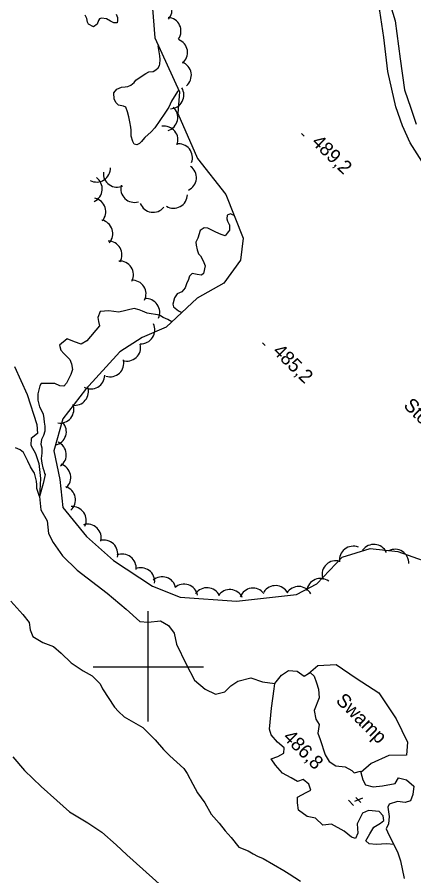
# Model space of a CAD drawing. Extents: x 642515 to 647219, y 6080136 to 6084356.
# Drawn here: x 642771.6 to 642857.9, y 6082154.5 to 6082341.5 of the extents above; entities that cross this region are included whole.
import ezdxf

# ---------------------------------------------------------------- set-up
doc = ezdxf.new("R2010")
doc.units = 0
for name, color, linetype in [('Level 1', 7, 'Continuous'), ('Level 2', 7, 'Continuous'), ('Level 21', 7, 'Continuous'), ('Level 3', 7, 'Continuous'), ('Level 4', 7, 'Continuous'), ('Level 44', 7, 'Continuous'), ('Level 54', 7, 'Continuous'), ('Level 61', 7, 'Continuous'), ('Level 7', 7, 'Continuous')]:
    doc.layers.add(name, color=color, linetype=linetype)

msp = doc.modelspace()

# ---------------------------------------------------------------- linework, layer by layer
at = {"layer": 'Level 1'}
for points in [[(642770.63, 6082180.44), (642773.23, 6082177.51), (642776.83, 6082173.98), (642780.24, 6082170.93), (642782.97, 6082168.49), (642787, 6082166.12), (642790.04, 6082164.02), (642793.11, 6082161.27), (642795.5, 6082159.13)], [(642795.5, 6082159.13), (642803.18, 6082152.26)]]:
    msp.add_lwpolyline(points, dxfattribs=at)
at = {"layer": 'Level 2'}
for points in [[(642793.11, 6082342.13), (642793.4, 6082341.41), (642793.47, 6082340.8), (642793.34, 6082340.23), (642792.65, 6082340.23), (642791.93, 6082340.64), (642791.01, 6082341.16), (642789.94, 6082341.26), (642789.54, 6082341.16), (642789.32, 6082340.74), (642789.04, 6082339.99), (642788.18, 6082339.37), (642787.09, 6082339.96), (642786.94, 6082340.4), (642786.73, 6082341.2), (642786.41, 6082341.96)], [(642806.78, 6082325.61), (642806.49, 6082325.28), (642805.18, 6082323.21), (642804.6, 6082321.88), (642803.74, 6082320.57), (642801.55, 6082317.37), (642800.79, 6082316.51), (642799.39, 6082315.29), (642798.97, 6082314.82), (642798.62, 6082314.44), (642798.2, 6082313.97), (642797.65, 6082313.69), (642797.07, 6082313.83), (642796.75, 6082314.42), (642796.44, 6082315.62), (642796.41, 6082316.88), (642796.33, 6082317.56), (642796.15, 6082318.73), (642795.93, 6082319.78), (642795.58, 6082320.85), (642795.24, 6082321.93), (642794.74, 6082322.15), (642793.67, 6082322.33), (642793.11, 6082322.83), (642792.74, 6082323.62), (642792.62, 6082325.04), (642793.27, 6082325.85), (642794.31, 6082326.23), (642795.12, 6082326.36), (642795.68, 6082326.39), (642796.32, 6082326.67), (642797.06, 6082327.24), (642797.4, 6082327.78), (642798.57, 6082328.58), (642799.63, 6082329.25), (642800.27, 6082329.61), (642801.2, 6082329.7), (642801.79, 6082330.02), (642802.29, 6082330.49), (642802.55, 6082330.95), (642802.66, 6082331.24), (642802.68, 6082332.3), (642802.64, 6082333.11), (642802.44, 6082334.36), (642802.33, 6082334.92), (642802.31, 6082335.28)], [(642818.83, 6082298.32), (642818.48, 6082298.49), (642817.98, 6082298.7), (642817.31, 6082298.38), (642817.24, 6082297.6), (642817.39, 6082297.08), (642817.76, 6082296.37), (642817.81, 6082296.25), (642817.8, 6082295.11), (642817.61, 6082294.82), (642817.31, 6082294.47), (642816.86, 6082293.88), (642815.98, 6082294.19), (642814.86, 6082294.65), (642813.09, 6082295.59), (642812.27, 6082295.62), (642811.45, 6082295.04), (642810.91, 6082293.38), (642810.51, 6082292.51), (642810.55, 6082291.86), (642810.78, 6082290.81), (642811.08, 6082289.94), (642811.47, 6082289.52), (642811.75, 6082289.05), (642812.21, 6082288.1), (642812.5, 6082287.38), (642812.12, 6082285.65), (642811.69, 6082285.34), (642810.75, 6082285.49), (642809.71, 6082285.71), (642809.06, 6082285.14), (642808.83, 6082284.19), (642808.54, 6082283.68), (642808.16, 6082282.56), (642807.4, 6082281.7), (642806.41, 6082281.27), (642805.81, 6082280.42), (642805.49, 6082279.02), (642805.65, 6082278.42), (642806.68, 6082277.59), (642807.4, 6082277.17)], [(642805.25, 6082275.16), (642804.35, 6082275.66), (642803.39, 6082276.14), (642802.59, 6082276.62), (642799.86, 6082277.06), (642798.86, 6082277.49), (642798.15, 6082277.74), (642797.07, 6082278.08), (642793.74, 6082277.29), (642791.53, 6082277.57), (642789.66, 6082277.39), (642789.16, 6082276.14), (642789.29, 6082275.26), (642789.51, 6082274.29), (642786.76, 6082271.05), (642785.5, 6082270.33), (642784.09, 6082270.82), (642782.51, 6082271.47), (642780.79, 6082270.07), (642781.09, 6082269.03), (642781.79, 6082268.26), (642783.08, 6082266.95), (642783.46, 6082265.99), (642783.61, 6082264.78), (642783.54, 6082264.54), (642783.26, 6082263.71), (642782.89, 6082262.96), (642782.31, 6082261.79), (642781.77, 6082261.19), (642780.87, 6082261.22), (642779.79, 6082261.73), (642776.86, 6082261.73), (642776.56, 6082261.22), (642776.09, 6082259.49), (642776.08, 6082258.11), (642776.49, 6082256.67), (642776.85, 6082256.04), (642777.23, 6082255.08), (642777.44, 6082254.12), (642777.49, 6082253.31), (642777.62, 6082252.42), (642777.6, 6082251.37), (642777.32, 6082250.38), (642776.88, 6082249.54), (642776.77, 6082248.56), (642776.98, 6082247.76), (642777.01, 6082246.58), (642776.82, 6082245.43), (642776.96, 6082244.38), (642777.22, 6082243.38)], [(642777.22, 6082243.38), (642777.38, 6082242.78), (642777.58, 6082242.14), (642777.67, 6082241.9), (642777.29, 6082239.93), (642776.45, 6082237.15), (642775.87, 6082238.91), (642775.91, 6082239.64), (642775.82, 6082240.49), (642775.36, 6082242.21), (642774.95, 6082242.88), (642774.51, 6082243.58), (642773.91, 6082244.81), (642772.99, 6082246.71), (642772.27, 6082247.28), (642771.23, 6082247.75)], [(642770.21, 6082214.36), (642772.81, 6082211.42), (642774.2, 6082209.72), (642774.45, 6082208.11), (642775.02, 6082206.68), (642777.21, 6082205.34), (642779.53, 6082204.49), (642781.15, 6082203.04), (642783.38, 6082200.89), (642786, 6082199.17), (642787.93, 6082198.06), (642789.65, 6082196.37), (642790.2, 6082195.26), (642792.77, 6082191.27), (642793.64, 6082190.34), (642794.92, 6082189.19), (642796.93, 6082188.01), (642798.95, 6082186.82), (642801.62, 6082184.13), (642803.44, 6082182.04), (642804.82, 6082180.65), (642807.89, 6082177.9), (642808.6, 6082176.8), (642809.79, 6082174.52), (642810.87, 6082172.63), (642812.45, 6082170.44), (642813.8, 6082168)], [(642813.8, 6082168), (642815.54, 6082165.99), (642816.85, 6082164.36), (642818.15, 6082162.89), (642819.81, 6082160.79), (642821.88, 6082160.01), (642822.98, 6082159.34), (642823.9, 6082158.82), (642825.15, 6082158.32), (642829.6, 6082155.73), (642830.77, 6082154.98), (642833.22, 6082153.41)]]:
    msp.add_lwpolyline(points, dxfattribs=at)
at = {"layer": 'Level 21'}
for points in [[(642890.16, 6082285.26), (642885.09, 6082288.73), (642879.91, 6082292), (642873.43, 6082296.81), (642867.14, 6082301.84), (642862.35, 6082306.82), (642860.11, 6082309.36), (642857.1, 6082314.12), (642855.4, 6082317.86), (642853.96, 6082321.97), (642852.23, 6082329.7), (642851.38, 6082337.04), (642850.53, 6082342.84), (642849.5, 6082346.74), (642847.42, 6082351.51), (642844.63, 6082358.06), (642842.31, 6082364.79), (642840.67, 6082368.86), (642839.51, 6082372.27), (642836.91, 6082377.66), (642833.29, 6082383.88), (642829.38, 6082390.21), (642825.57, 6082397.07)], [(642852.81, 6082344.03), (642853.85, 6082340.73), (642854.92, 6082332.44), (642855.9, 6082325.68), (642857.22, 6082321.68), (642858.38, 6082318.19)]]:
    msp.add_lwpolyline(points, dxfattribs=at)
at = {"layer": 'Level 3'}
for p, q in [((642833.45, 6082316.13), (642834.02, 6082315.57)), ((642825, 6082270.6), (642825.57, 6082270.04)), ((642843.66, 6082170.99), (642844.79, 6082169.86)), ((642846.73, 6082171.47), (642844.96, 6082170.74)), ((642845.28, 6082171.63), (642846.39, 6082170.53))]:
    msp.add_line(p, q, dxfattribs=at)
at = {"layer": 'Level 4'}
for points in [[(642771.06, 6082265.43), (642773.75, 6082259.34), (642775.9, 6082252.82), (642776.01, 6082250.88), (642774.69, 6082249.76), (642774.61, 6082248.3), (642775.61, 6082246.49), (642776.29, 6082244.34), (642776.72, 6082241.05), (642776.45, 6082237.15), (642776.78, 6082234.25), (642778.13, 6082231.82), (642778.44, 6082229.09), (642779.44, 6082227.12), (642781.46, 6082224.24), (642784.63, 6082221.09), (642791.22, 6082216.11), (642795.29, 6082212.61), (642798.27, 6082209.94), (642800.14, 6082209.8), (642802.8, 6082210.03), (642804.55, 6082209.07), (642805.78, 6082207.36), (642806.24, 6082204.96), (642808.34, 6082200.62), (642810.15, 6082197.16), (642812.52, 6082195.19), (642814.77, 6082194.1), (642816.76, 6082194.61), (642818.06, 6082195.89), (642819.62, 6082196.95), (642822.41, 6082197.66), (642825, 6082196.78), (642827.69, 6082196.44)], [(642827.69, 6082196.44), (642829.13, 6082198.22), (642830.6, 6082199.27), (642832.51, 6082199.09), (642834.07, 6082198), (642834.99, 6082198.59), (642835.32, 6082198.8), (642836.25, 6082198.04), (642836.7, 6082196.57), (642837.18, 6082195.22), (642837.28, 6082193.28), (642836.19, 6082190.52), (642836.61, 6082188.68), (642837.32, 6082187.51), (642836.99, 6082185.59), (642837.51, 6082184.2), (642838.62, 6082180.91), (642839.47, 6082179.46), (642840.94, 6082178.53), (642842.97, 6082178.31), (642844.39, 6082177.5), (642844.95, 6082177), (642846.26, 6082177.36), (642846.34, 6082177.07), (642846.77, 6082175.45), (642847.4, 6082174.35), (642849.04, 6082173.95), (642851.05, 6082174.14), (642853.81, 6082174.66), (642854.59, 6082175.87), (642856.31, 6082175.48), (642857.88, 6082174.07), (642857.7, 6082172.24), (642857.17, 6082170.88), (642855.98, 6082170.49), (642854.31, 6082170.76), (642852.56, 6082170.18), (642852.24, 6082169.48), (642852.51, 6082167.47), (642852.4, 6082165.89), (642851.89, 6082164.81), (642852.49, 6082163.51), (642853.55, 6082161.36), (642852.01, 6082161.51), (642849.67, 6082161.37), (642848.21, 6082161.53), (642847.44, 6082162.14), (642848.33, 6082163.72), (642849.22, 6082165.15), (642850.66, 6082165.99), (642851.36, 6082166.6), (642851.26, 6082167.6), (642850.36, 6082168.56), (642848.04, 6082168.8), (642846.74, 6082168.21), (642845.58, 6082165.88), (642845.69, 6082163.86), (642845.19, 6082162.71), (642844.37, 6082162.98), (642842.76, 6082164.27), (642840, 6082165.82), (642838.08, 6082165.55), (642836.54, 6082167.09), (642834.7, 6082167.43), (642832.8, 6082168.82), (642832.59, 6082170.47), (642832.6, 6082171.68), (642834.49, 6082172.68), (642835.51, 6082173.22), (642835.07, 6082174.53), (642833.8, 6082175.51), (642832.61, 6082175.12), (642831.23, 6082175.89), (642829.36, 6082176.88), (642827.77, 6082178.62), (642826.88, 6082180.02), (642828.31, 6082180.51), (642829.64, 6082181.23), (642829.66, 6082182.44), (642828.26, 6082183.62), (642826.87, 6082185.24), (642826.52, 6082186.47), (642826.95, 6082191.06), (642827.48, 6082195.26), (642827.69, 6082196.44)], [(642853.55, 6082161.36), (642854.42, 6082159.59), (642854.97, 6082157.81), (642855.81, 6082153.96)]]:
    msp.add_lwpolyline(points, dxfattribs=at)
at = {"layer": 'Level 44'}
for centre, start, end in [((642802.3, 6082343.08), 317.7481, 77.726), ((642804.25, 6082338.45), 325.5456, 85.5235), ((642805.67, 6082333.79), 309.4944, 69.4723), ((642806.5, 6082328.86), 309.4944, 69.4723), ((642804.87, 6082324.54), 271.363, 31.3409), ((642803.54, 6082319.66), 287.896, 47.874), ((642803.58, 6082314.77), 339.286, 99.2639), ((642806.75, 6082310.9), 339.286, 99.2639), ((642807.6, 6082306.57), 294.5583, 54.5363), ((642788.89, 6082308.6), 242.3535, 2.3314), ((642793.35, 6082307.48), 174.8147, 294.7926), ((642787.12, 6082304.11), 294.8945, 54.8725), ((642797.14, 6082304.17), 166.0194, 285.9974), ((642787.9, 6082299.15), 317.7218, 77.6997), ((642805.64, 6082302.89), 239.0759, 359.0539), ((642801.19, 6082302.01), 201.1064, 321.0844), ((642789.42, 6082294.38), 317.7218, 77.6997), ((642791.39, 6082289.75), 329.8817, 89.8597), ((642793.91, 6082285.41), 333.0868, 93.0647), ((642796.64, 6082281.22), 333.0868, 93.0647), ((642799.63, 6082277.21), 335.3209, 95.2989), ((642798.56, 6082273.39), 266.9595, 26.9374), ((642795.47, 6082269.6), 252.9549, 12.9328), ((642791.81, 6082266.19), 252.9549, 12.9328), ((642787.66, 6082263.56), 239.7121, 359.69), ((642784.11, 6082259.98), 260.7503, 20.7282), ((642780.95, 6082256.11), 260.7503, 20.7282), ((642779.31, 6082251.27), 281.8817, 41.8597), ((642779.3, 6082246.23), 305.7573, 65.7352), ((642780.26, 6082241.29), 311.9725, 71.9504), ((642781.3, 6082236.4), 311.9725, 71.9504), ((642783.63, 6082231.94), 334.8871, 94.865), ((642786.9, 6082228.11), 346.1387, 106.1166), ((642790.5, 6082224.64), 346.1387, 106.1166), ((642849.19, 6082223.71), 24.7694, 144.7473), ((642844.7, 6082223.31), 67.987, 187.9649), ((642853.81, 6082222.64), 357.6984, 117.6763), ((642794.5, 6082221.59), 353.4829, 113.4609), ((642840.93, 6082220.16), 81.1316, 201.1095), ((642798.52, 6082218.62), 353.4829, 113.4609), ((642803.17, 6082216.64), 11.4085, 131.3864), ((642837.58, 6082216.3), 53.2358, 173.2137), ((642807.91, 6082215.04), 11.4085, 131.3864), ((642827.81, 6082214.73), 28.0118, 147.9897), ((642832.81, 6082214.55), 28.0118, 147.9897), ((642812.89, 6082214.28), 25.2808, 145.2588), ((642817.87, 6082213.87), 25.2808, 145.2588), ((642822.9, 6082214.18), 37.7255, 157.7034)]:
    msp.add_arc(centre, 3, start, end, dxfattribs=at)
at = {"layer": 'Level 54'}
msp.add_lwpolyline([(642800.84, 6082346.19), (642801.52, 6082337.01), (642806.95, 6082325.25), (642806.56, 6082320.54), (642810.83, 6082310.74), (642817.02, 6082302.9), (642820.78, 6082293.4), (642820.16, 6082288.6), (642816.57, 6082283.56), (642810.77, 6082280.34), (642804.01, 6082274), (642798.8, 6082271.78), (642793.97, 6082268.61), (642786.5, 6082260.45), (642781.53, 6082254.04), (642779.58, 6082247.06), (642780.9, 6082240.83), (642781.56, 6082234.72), (642786.68, 6082228.45), (642792.55, 6082223.19), (642801.03, 6082217.59), (642807.06, 6082215.25), (642819.31, 6082214.37), (642832.39, 6082215.81), (642836.79, 6082218.15), (642842.28, 6082223.94), (642848.39, 6082225.8), (642854.4, 6082225.16), (642860.91, 6082222.84)], dxfattribs=at)
at = {"layer": 'Level 61'}
for p, q in [((642800, 6082212.16), (642800, 6082188.16)), ((642812.16, 6082200), (642788.16, 6082200))]:
    msp.add_line(p, q, dxfattribs=at)
at = {"layer": 'Level 7'}
msp.add_lwpolyline([(642834.99, 6082198.59), (642837.01, 6082200.32), (642841.02, 6082200.59), (642845.34, 6082197.57), (642850.27, 6082194.39), (642854.08, 6082188.76), (642856.52, 6082183.65), (642856.31, 6082180.84), (642852.45, 6082180.75), (642848.6, 6082179.03), (642846.34, 6082177.07)], dxfattribs=at)

# ---------------------------------------------------------------- texts
at = {"layer": 'Level 3'}
for s, rotation, p in [('489,2', 315.59, (642835.48, 6082314.08)), ('485,2', 315.59, (642827.02, 6082268.55)), ('  486,8', 315.1735, (642827.7, 6082186.11))]:
    msp.add_text(s, height=3, rotation=rotation, dxfattribs=at).set_placement(p)
at = {"layer": 'Level 54'}
msp.add_text('Stone pit', height=3, rotation=315.1749, dxfattribs=at).set_placement((642855.47, 6082256.78))
at = {"layer": 'Level 7'}
msp.add_text('Swamp', height=3, rotation=315.1749, dxfattribs=at).set_placement((642840.75, 6082192.52))

doc.saveas('drawing.dxf')
